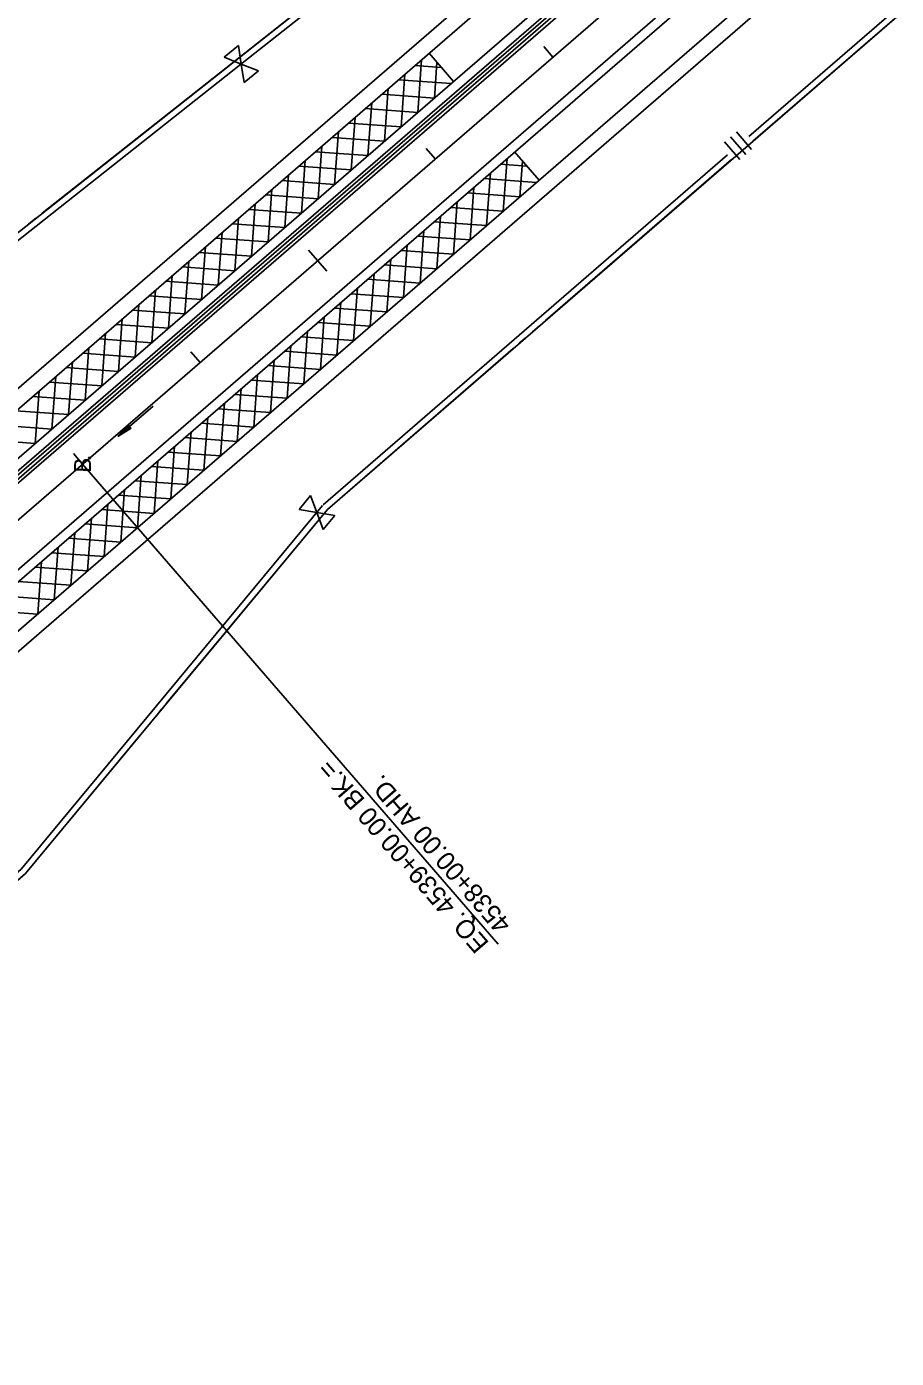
# Model space of a CAD drawing. Extents: x 192699 to 285914, y 194342 to 233219.
# Drawn here: x 203517 to 204077, y 202501 to 203358 of the extents above; entities that cross this region are included whole.
import ezdxf

# ---------------------------------------------------------------- set-up
doc = ezdxf.new("R2010")
doc.units = 0
for name, color, linetype in [('CENT LINE', 7, 'Continuous'), ('CONCRETE', 7, 'Continuous'), ('CURVE DATA', 7, 'Continuous'), ('DRAINAGE', 7, 'Continuous'), ('DRAINAGE ARROWS', 7, 'Continuous'), ('PAVEMENT TRANSITION', 7, 'Continuous'), ('R-W - CofA', 7, 'Continuous'), ('R_Water Annot', 7, 'Continuous'), ('ROAD', 7, 'Continuous'), ('SHOULDER', 7, 'Continuous'), ('STATIONING1', 7, 'Continuous'), ('TEXT', 7, 'Continuous'), ('WRSF', 7, 'Continuous')]:
    doc.layers.add(name, color=color, linetype=linetype)

msp = doc.modelspace()

# ---------------------------------------------------------------- linework, layer by layer
at = {"layer": 'CENT LINE'}
msp.add_line((198833.18, 198989.86), (207514.58, 206505.51), dxfattribs=at)
at = {"layer": 'CONCRETE'}
for p, q in [((203078.95, 202694.61), (207308.06, 206355.82)), ((203081.57, 202691.58), (207310.61, 206352.73))]:
    msp.add_line(p, q, dxfattribs=at)
at = {"layer": 'DRAINAGE'}
msp.add_line((203558.6, 203079.42), (203557.29, 203080.93), dxfattribs=at)
at = {"layer": 'DRAINAGE ARROWS'}
for p, q in [((203582.73, 203101.68), (203576.17, 203093.99)), ((203584.7, 203099.42), (203576.17, 203093.99)), ((203582.9, 203101.49), (203577.43, 203095.08)), ((203584.54, 203099.6), (203577.43, 203095.08)), ((203583.06, 203101.3), (203578.73, 203096.21)), ((203584.37, 203099.8), (203578.73, 203096.21)), ((203583.23, 203101.11), (203579.98, 203097.3)), ((203584.21, 203099.99), (203579.98, 203097.3)), ((203583.39, 203100.92), (203581.26, 203098.42)), ((203584.03, 203100.18), (203581.26, 203098.42)), ((203583.56, 203100.72), (203582.52, 203099.51)), ((203583.87, 203100.37), (203582.52, 203099.51)), ((203584.7, 203099.42), (203582.73, 203101.68))]:
    msp.add_line(p, q, dxfattribs=at)
at = {"layer": 'PAVEMENT TRANSITION'}
for p, q in [((203768.96, 203302.54), (203771.4, 203336.4)), ((203776.25, 203340.59), (203791.96, 203322.45)), ((203779.66, 203311.8), (203781.31, 203334.75)), ((203758.27, 203293.29), (203760.71, 203327.14)), ((203767.19, 203332.75), (203784.09, 203331.53)), ((203747.58, 203284.03), (203750.02, 203317.88)), ((203756.49, 203323.49), (203790.35, 203321.05)), ((203790.35, 203321.05), (203790.35, 203321.05)), ((203736.89, 203274.77), (203739.32, 203308.63)), ((203745.8, 203314.24), (203779.66, 203311.8)), ((203726.2, 203265.52), (203728.63, 203299.37)), ((203735.11, 203304.98), (203768.96, 203302.54)), ((203724.42, 203295.72), (203758.27, 203293.29)), ((203713.73, 203286.47), (203747.58, 203284.03)), ((203715.5, 203256.26), (203717.94, 203290.11)), ((203703.03, 203277.21), (203736.89, 203274.77)), ((203704.81, 203247), (203707.25, 203280.86)), ((203831.23, 203277.09), (203846.94, 203258.94)), ((203692.34, 203267.95), (203726.2, 203265.52)), ((203694.12, 203237.75), (203696.56, 203271.6)), ((203822.17, 203269.24), (203839.08, 203268.02)), ((203823.94, 203239.03), (203826.38, 203272.89)), ((203834.64, 203248.29), (203836.29, 203271.25)), ((203681.65, 203258.7), (203715.5, 203256.26)), ((203683.43, 203228.49), (203685.86, 203262.35)), ((203811.47, 203259.98), (203845.33, 203257.55)), ((203813.25, 203229.78), (203815.69, 203263.63)), ((203845.33, 203257.55), (203845.33, 203257.55)), ((203670.96, 203249.44), (203704.81, 203247)), ((203672.74, 203219.24), (203675.17, 203253.09)), ((203800.78, 203250.73), (203834.64, 203248.29)), ((203802.56, 203220.52), (203805, 203254.38)), ((203660.27, 203240.18), (203694.12, 203237.75)), ((203662.04, 203209.98), (203664.48, 203243.83)), ((203790.09, 203241.47), (203823.94, 203239.03)), ((203791.87, 203211.27), (203794.3, 203245.12)), ((203649.57, 203230.93), (203683.43, 203228.49)), ((203651.35, 203200.72), (203653.79, 203234.58)), ((203779.4, 203232.21), (203813.25, 203229.78)), ((203781.18, 203202.01), (203783.61, 203235.86)), ((203640.66, 203191.47), (203643.1, 203225.32)), ((203768.71, 203222.96), (203802.56, 203220.52)), ((203770.48, 203192.75), (203772.92, 203226.61)), ((203629.97, 203182.21), (203632.4, 203216.06)), ((203638.88, 203221.67), (203672.74, 203219.24)), ((203758.01, 203213.7), (203791.87, 203211.27)), ((203759.79, 203183.5), (203762.23, 203217.35)), ((203619.27, 203172.95), (203621.71, 203206.81)), ((203628.19, 203212.42), (203662.04, 203209.98)), ((203749.1, 203174.24), (203751.54, 203208.09)), ((203608.58, 203163.7), (203611.02, 203197.55)), ((203617.5, 203203.16), (203651.35, 203200.72)), ((203738.41, 203164.98), (203740.84, 203198.84)), ((203747.32, 203204.45), (203781.18, 203202.01)), ((203597.89, 203154.44), (203600.33, 203188.3)), ((203606.81, 203193.9), (203640.66, 203191.47)), ((203727.72, 203155.73), (203730.15, 203189.58)), ((203736.63, 203195.19), (203770.48, 203192.75)), ((203596.11, 203184.65), (203629.97, 203182.21)), ((203717.02, 203146.47), (203719.46, 203180.33)), ((203725.94, 203185.93), (203759.79, 203183.5)), ((203585.42, 203175.39), (203619.28, 203172.95)), ((203587.2, 203145.18), (203589.64, 203179.04)), ((203706.33, 203137.21), (203708.77, 203171.07)), ((203715.25, 203176.68), (203749.1, 203174.24)), ((203574.73, 203166.13), (203608.58, 203163.7)), ((203576.51, 203135.93), (203578.94, 203169.78)), ((203704.55, 203167.42), (203738.41, 203164.98)), ((203564.04, 203156.88), (203597.89, 203154.44)), ((203565.81, 203126.67), (203568.25, 203160.53)), ((203693.86, 203158.16), (203727.72, 203155.73)), ((203695.64, 203127.96), (203698.08, 203161.81)), ((203553.34, 203147.62), (203587.2, 203145.18)), ((203555.12, 203117.42), (203557.56, 203151.27)), ((203683.17, 203148.91), (203717.02, 203146.47)), ((203684.95, 203118.7), (203687.38, 203152.56)), ((203542.65, 203138.37), (203576.51, 203135.93)), ((203544.43, 203108.16), (203546.87, 203142.01)), ((203672.48, 203139.65), (203706.33, 203137.21)), ((203674.25, 203109.45), (203676.69, 203143.3)), ((203531.96, 203129.11), (203565.81, 203126.67)), ((203533.74, 203098.9), (203536.17, 203132.76)), ((203661.79, 203130.4), (203695.64, 203127.96)), ((203663.56, 203100.19), (203666, 203134.04)), ((203521.27, 203119.85), (203555.12, 203117.42)), ((203523.05, 203089.65), (203525.48, 203123.5)), ((203651.09, 203121.14), (203684.95, 203118.7)), ((203652.87, 203090.93), (203655.31, 203124.79)), ((203640.4, 203111.88), (203674.26, 203109.45)), ((203642.18, 203081.68), (203644.62, 203115.53)), ((203510.58, 203110.6), (203544.43, 203108.16)), ((203629.71, 203102.63), (203663.56, 203100.19)), ((203631.49, 203072.42), (203633.92, 203106.27)), ((203499.88, 203101.34), (203533.74, 203098.9)), ((203620.79, 203063.16), (203623.23, 203097.02)), ((203489.19, 203092.08), (203523.05, 203089.65)), ((203610.1, 203053.91), (203612.54, 203087.76)), ((203619.02, 203093.37), (203652.87, 203090.93)), ((203599.41, 203044.65), (203601.85, 203078.51)), ((203608.32, 203084.11), (203642.18, 203081.68)), ((203588.72, 203035.39), (203591.15, 203069.25)), ((203597.63, 203074.86), (203631.49, 203072.42)), ((203578.03, 203026.14), (203580.46, 203059.99)), ((203586.94, 203065.6), (203620.79, 203063.16)), ((203567.33, 203016.88), (203569.77, 203050.74)), ((203576.25, 203056.34), (203610.1, 203053.91)), ((203565.56, 203047.09), (203599.41, 203044.65)), ((203554.86, 203037.83), (203588.72, 203035.4)), ((203556.64, 203007.63), (203559.08, 203041.48)), ((203544.17, 203028.58), (203578.03, 203026.14)), ((203545.95, 202998.37), (203548.39, 203032.22)), ((203533.48, 203019.32), (203567.33, 203016.88)), ((203535.26, 202989.11), (203537.69, 203022.97)), ((203522.79, 203010.06), (203556.64, 203007.63)), ((203524.57, 202979.86), (203527, 203013.71)), ((203512.1, 203000.81), (203545.95, 202998.37)), ((203501.4, 202991.55), (203535.26, 202989.11)), ((203490.71, 202982.29), (203524.57, 202979.86))]:
    msp.add_line(p, q, dxfattribs=at)
at = {"layer": 'R-W - CofA'}
for p, q in [((203644.42, 203338.09), (203653.78, 203345.49)), ((203653.78, 203345.49), (203655.51, 203333.68)), ((203655.51, 203333.68), (203644.42, 203338.09)), ((203657.24, 203321.88), (203655.51, 203333.68)), ((203655.51, 203333.68), (203666.6, 203329.28)), ((203666.6, 203329.28), (203657.24, 203321.88)), ((203966.23, 203283.54), (203976.06, 203272.18)), ((203970.01, 203286.81), (203979.85, 203275.45)), ((203973.8, 203290.09), (203983.63, 203278.73)), ((203692.62, 203047.18), (203700.04, 203056.13)), ((203700.04, 203056.13), (203704.08, 203045.24)), ((203704.08, 203045.24), (203692.62, 203047.18)), ((203708.12, 203034.34), (203704.08, 203045.24)), ((203704.08, 203045.24), (203715.54, 203043.29)), ((203715.54, 203043.29), (203708.12, 203034.34))]:
    msp.add_line(p, q, dxfattribs=at)
for points in [[(203710.83, 203047.2), (206205.77, 205207.11), (206442.4, 205392.13), (207485.74, 206295.37)], [(203660.19, 203337.39), (203776.59, 203429.44), (203927.41, 203560.01)], [(203981.74, 203287.03), (204246.12, 203515.9)], [(203657.68, 203340.56), (203774.01, 203432.56), (203782.82, 203440.19)], [(203067.39, 202873.74), (203774.01, 203432.56)], [(203984.36, 203284), (204103.94, 203387.52)], [(203382.78, 203118), (203660.19, 203337.39)], [(203527.53, 203237.64), (203657.68, 203340.56)], [(203708.2, 203050.22), (203968.12, 203275.24)], [(203851.16, 203168.69), (203970.74, 203272.21)], [(203518.65, 203230.62), (203523.49, 203234.44)], [(203842.7, 203161.37), (203847.32, 203165.36)], [(203834.24, 203154.04), (203838.86, 203158.04)], [(203710.83, 203047.2), (203830.4, 203150.71)], [(198915, 198895.36), (200006.21, 199840.04), (200088.36, 199897.93), (200242.84, 200025.06), (200696.47, 200417.77), (200850.95, 200544.9), (200998.89, 200679.58), (203115.81, 202512.24), (203289.93, 202616.68), (203516.74, 202813.04), (203710.83, 203047.2)], [(203483.67, 202789.62), (203513.91, 202815.81), (203707.79, 203049.71)], [(203607.69, 202922.77), (203710.83, 203047.2)], [(203600.66, 202914.28), (203604.49, 202918.91)], [(203593.62, 202905.8), (203597.46, 202910.43)], [(203486.25, 202786.64), (203516.74, 202813.04), (203590.43, 202901.94)]]:
    msp.add_lwpolyline(points, dxfattribs=at)
at = {"layer": 'R_Water Annot'}
for p, q in [((203598.81, 203113.67), (203576.17, 203093.99)), ((203582.73, 203101.68), (203576.17, 203093.99)), ((203584.7, 203099.42), (203576.17, 203093.99)), ((203582.9, 203101.49), (203577.43, 203095.08)), ((203584.54, 203099.6), (203577.43, 203095.08)), ((203583.06, 203101.3), (203578.73, 203096.21)), ((203584.37, 203099.8), (203578.73, 203096.21)), ((203583.23, 203101.11), (203579.98, 203097.3)), ((203584.21, 203099.99), (203579.98, 203097.3)), ((203583.39, 203100.92), (203581.26, 203098.42)), ((203584.03, 203100.18), (203581.26, 203098.42)), ((203583.56, 203100.72), (203582.52, 203099.51)), ((203583.87, 203100.37), (203582.52, 203099.51)), ((203584.7, 203099.42), (203582.73, 203101.68))]:
    msp.add_line(p, q, dxfattribs=at)
at = {"layer": 'ROAD'}
for p, q in [((198797.83, 199030.68), (207479.24, 206546.34)), ((198813.54, 199012.54), (207494.94, 206528.19)), ((198852.81, 198967.18), (207534.22, 206482.83)), ((198868.52, 198949.03), (207549.92, 206464.68))]:
    msp.add_line(p, q, dxfattribs=at)
at = {"layer": 'SHOULDER'}
for p, q in [((203018.88, 202698.15), (207472.69, 206553.9)), ((203077.65, 202696.12), (207498.87, 206523.66)), ((203109.06, 202659.83), (207530.29, 206487.37)), ((203088.41, 202589.04), (207556.47, 206457.12))]:
    msp.add_line(p, q, dxfattribs=at)
at = {"layer": 'STATIONING1'}
for points in [[(203849.93, 203344.86), (203855.82, 203338.06)], [(203774.33, 203279.41), (203780.22, 203272.61)], [(203698.73, 203213.96), (203710.51, 203200.35)], [(203623.12, 203148.51), (203629.01, 203141.7)], [(203547.52, 203083.05), (203553.41, 203076.25)]]:
    msp.add_lwpolyline(points, dxfattribs=at)
at = {"layer": 'TEXT'}
msp.add_lwpolyline([(203820.65, 202767.59), (203553.39, 203076.27)], dxfattribs=at)
at = {"layer": 'WRSF'}
msp.add_line((203046.29, 202663.68), (207309.33, 206354.28), dxfattribs=at)

# ---------------------------------------------------------------- texts
at = {"layer": 'CURVE DATA'}
msp.add_text('B', height=10.85, rotation=88.88334, dxfattribs=at).set_placement((203558.73, 203070.71))
at = {"layer": 'TEXT'}
for s, p in [('EQ. 4539+00.00 BK.=', (203815.31, 202768.32)), ('4538+00.00 AHD.', (203829.67, 202780.76))]:
    msp.add_text(s, height=12, rotation=130.88334, dxfattribs=at).set_placement(p)

doc.saveas('drawing.dxf')
